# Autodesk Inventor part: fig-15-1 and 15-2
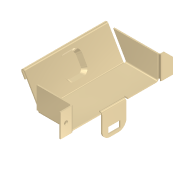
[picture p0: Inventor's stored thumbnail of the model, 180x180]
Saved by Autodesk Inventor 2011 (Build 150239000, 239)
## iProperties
Shininess: 65.0
Angle Display Precision: 2
Document Length Units: 11269
Document Angle Units: 11279
Document Time Units: 11290
Document Mass Units: 11283
Document Length Units Precision: 3
Document Angle Units Precision: 2
Compacted: False
Created: 2002-04
Part Number: fig-15-1 and 15-2
Material: Stainless Steel, 440C
Document SubType Name: Sheet Metal
Density: 1 g/cm^3
Sheet Metal Rule: Default
Density: 0.0
Volumn: 0.0
Area: 0.0
PropertySet Name: Model Information
Control State: 0
Master: False
Checked Out: False
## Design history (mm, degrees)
node "Face1"
  sketch "Sketch1"
    geometry: L1 (-46.618, 22.343)-(-46.618, -12.657); L2 (-46.618, -12.657)-(53.382, -12.657); L3 (53.382, -12.657)-(53.382, 22.343); L4 (53.382, 22.343)-(35.882, 22.343); L5 (35.882, 22.343)-(35.882, 12.343); L6 (35.882, 12.343)-(-29.118, 12.343); L7 (-29.118, 12.343)-(-29.118, 22.343); L8 (-29.118, 22.343)-(-46.618, 22.343)
    constraints: 16 end point, 6 parallel, 2 equal length, 1 perpendicular, 1 vertical
    dimensions: "d0" = 100 distance of L1.end L2.end; "d1" = 35 distance of L1.start L1.end; "d2" = 65 distance of L5.end L6.end; "d3" = 10 distance of L6.end L7.end
sketch "Sketch2"
  geometry: L1 (100, 0)-(0, 0) reference; L2 (17.5, 35)-(17.5, 25) reference; L3 (17.5, 25)-(17.5, 0); L4 (82.5, 25)-(82.5, 0)
  constraints: 4 end point, 2 point on line, 1 collinear, 1 perpendicular
feature "Fold1" dims "d5" = 1 (= BendRadius), "d6" = 90 deg, "d7" = 1 (= BendRadius), "d52" = 1 (= BendReliefWidth), "d53" = 0.5 (= BendReliefDepth), "d54" = 2 (= MinimumRemnant), "SeamGap" = 0.01, "Thickness" = 1
feature "Fold2" dims "d8" = 1 (= BendRadius), "d9" = 90 deg, "d10" = 1 (= BendRadius), "d55" = 1 (= BendReliefWidth), "d56" = 0.5 (= BendReliefDepth), "d57" = 2 (= MinimumRemnant), "SeamGap" = 0.01, "Thickness" = 1
node "Flange1"
feature "Corner1" dims "d15" = 1 (= Thickness), "d16" = 0, "d73" = 4 (= CornerReliefSize), "Thickness" = 1, "TransitionRadius" = 1 (= BendRadius)
sketch "Sketch4"
  geometry: L1 (0, 0)-(0, 35) reference; L2 (15.869, 25)-(15.869, 26) reference; L3 (17.5, 26)-(0, 26)
  constraints: 2 end point, 1 perpendicular, 1 point on line
feature "Fold3" sketch "Sketch4" dims "d17" = 1 (= BendRadius), "d18" = 90 deg, "d19" = 1 (= BendRadius), "d61" = 1 (= BendReliefWidth), "d62" = 0.5 (= BendReliefDepth), "d63" = 2 (= MinimumRemnant), "SeamGap" = 0.01, "Thickness" = 1
sketch "Sketch5"
  geometry: L1 (-17.5, -34.296)-(-17.5, 9) reference; L2 (0, 0)-(-17.5, 0)
  constraints: 2 end point, 1 perpendicular, 1 point on line
feature "Fold4" sketch "Sketch5" dims "d20" = 1 (= BendRadius), "d21" = 90 deg, "d22" = 1 (= BendRadius), "d64" = 1 (= BendReliefWidth), "d65" = 0.5 (= BendReliefDepth), "d66" = 2 (= MinimumRemnant), "SeamGap" = 0.01, "Thickness" = 1
sketch "Sketch6"
  geometry: 1 further point
feature "iFeature4:1" sketch "Sketch6"
feature "Hem2" dims "d32" = 1 (= BendRadius), "d33" = 6 (= 6 x Thickness), "d34" = 1 (= Thickness), "d35" = 0.5 (= 0.5 x d34), "d67" = 1 (= BendReliefWidth), "d68" = 0.5 (= BendReliefDepth), "d69" = 2 (= MinimumRemnant), "SeamGap" = 0.01, "Thickness" = 1, "MinimumRemnant" = 2 (= 2 x Thickness), "BendReliefWidth" = 1 (= Thickness)
node "Face2"
  sketch "Sketch9"
    geometry: L1 (0, 0)-(62.738, 0) reference; L2 (40.511, 0)-(22.35, 0); L3 (22.35, 0)-(22.35, 18.987); L4 (22.35, 18.987)-(40.511, 18.987); L5 (40.511, 18.987)-(40.511, 0)
    constraints: 8 end point, 2 parallel, 1 horizontal, 1 perpendicular, 1 point on line
sketch "Sketch10"
  geometry: L1 (13.661, -2.202)-(4.661, -2.202); L2 (4.661, -2.202)-(4.661, -7.127); L3 (4.661, -7.127)-(13.661, -7.127); L4 (13.661, -7.127)-(13.661, -2.202); L5 (18.161, -16.987)-(18.161, 0) reference
  constraints: 8 end point, 2 parallel, 1 horizontal, 1 perpendicular
  dimensions: "d50" = 4.5 distance between parallel lines of L5 L4; "d51" = 9 distance of L1.start L1.end
cut "Cut1" sketch "Sketch10" dims "d38" = 1 (= Thickness), "d39" = 0
sketch "Sketch11"
  geometry: 1 further point
hole "Hole1" sketch "Sketch11" at (3.935, 8.75) diameter "d40" = 3; stored, may be unused: countersink angle "d44" = 82 deg, drill point angle "d46" = 118 deg; dims "d41" = 6, "d42" = 4, "d43" = 2, "d45" = 8
feature "Corner Chamfer1" dims "d47" = 6, "d48" = 6, angle "d74" = 45 deg
feature "Corner Round1" dims "d49" = 6
body "Solid1"
face "Plate1" dims "Thickness" = 1
sketch "Sketch3"
  geometry: L1 (62.738, 0)-(62.738, -25); L2 (62.738, -25)-(0, -25); 2 other entities
  constraints: 4 end point, 4 other
face "Plate2" dims "d12" = 25, "d13" = 120 deg, "d14" = 1 (= BendRadius), "Thickness" = 1, "MinimumRemnant" = 2 (= 2 x Thickness), "BendReliefWidth" = 1 (= Thickness)
bend "Bend1" dims "d11" = 1 (= BendRadius), "d12" = 25, "d13" = 120 deg, "d14" = 1 (= BendRadius), "d58" = 1 (= BendReliefWidth), "d59" = 0.5 (= BendReliefDepth), "d60" = 2 (= MinimumRemnant), "SeamGap" = 0.01, "Thickness" = 1, "MinimumRemnant" = 2 (= 2 x Thickness), "BendReliefWidth" = 1 (= Thickness)
sketch "Sketch8"
  geometry: L1 (0.866, 0.5)-(0, 0); L2 (-0.866, -0.5)-(1.384, -4.397); L3 (1.384, -4.397)-(0.518, -4.897); L4 (0.518, -4.897)-(-1.732, -1); A1 r 0.5 centre (-0.433, -0.25) between (0, 0) and (-0.866, -0.5); A2 r 1.5 centre (-0.433, -0.25) between (0.866, 0.5) and (-1.732, -1)
  constraints: 8 end point, 4 point on circle
face "Plate3" dims "d36" = 1 (= BendRadius), "Thickness" = 1, "MinimumRemnant" = 2 (= 2 x Thickness), "BendReliefWidth" = 1 (= Thickness)
bend "Bend2" dims "d36" = 1 (= BendRadius), "d37" = 1 (= BendRadius), "d70" = 1 (= BendReliefWidth), "d71" = 0.5 (= BendReliefDepth), "d72" = 2 (= MinimumRemnant), "SeamGap" = 0.01, "Thickness" = 1, "MinimumRemnant" = 2 (= 2 x Thickness), "BendReliefWidth" = 1 (= Thickness)
other parameters: "BendRadius" = 1 (= Thickness), "BendReliefDepth" = 0.5 (= 0.5 x Thickness), "CornerReliefSize" = 4 (= 4 x Thickness), "d4" = 1 (= BendRadius), "d27" = 0, "JacobiRadiusSize" = 1 (= Thickness), "GapSize" = 1 (= Thickness)
